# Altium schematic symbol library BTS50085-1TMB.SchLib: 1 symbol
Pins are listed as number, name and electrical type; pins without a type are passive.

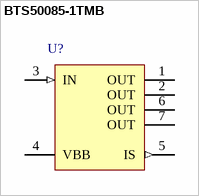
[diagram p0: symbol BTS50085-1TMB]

## BTS50085-1TMB
designator U?
Smart Highside High Current Power Switch, 1 Channel, 44 A Load Current, -40 to 150 degC, PG-TO220-7-11, Tube, Green; Manufacturer: Infineon; PartNumber: BTS50085-1TMB; Channels: 1; Green: TRUE; Group: Automotive Qualified; Load Current (typ): 44 A; Packing: Reel; Ptot (max): 170 W; Recommended Operating Voltage Max.: 58 V; Recommended Operating Voltage Min.: 5 V; RON @ 25degreesC: 9 mOhm; RON(max) @ 150degreesC: 17 mOhm; toff (max): 110 us; ton (max): 400 us
footprint INF-PG-TO220-7-11 (FM, 7-Leads, Body 10x9.25mm, Pitch 1.27mm)
pins: 1 OUT (power) "Output to the load. The pins1,2,6 and 7 must be shorted with each other especially in high current applications!", 2 OUT (power) "Output to the load. The pins1,2,6 and 7 must be shorted with each other especially in high current applications!", 3 IN (in) "Input, activates the power switch in case of short to ground", 4 VBB (power) "Positive power supply voltage, the tab is electrically connected to this pin. In high current applications the tab should be used for the Vbb connection instead of this pin", 5 IS (out) "Diagnostic feedback providing a sense current proportional to the load current; zero current on failure (see Truth Table on page 7)", 6 OUT (power) "Output to the load. The pins1,2,6 and 7 must be shorted with each other especially in high current applications!", 7 OUT (power) "Output to the load. The pins1,2,6 and 7 must be shorted with each other especially in high current applications!"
